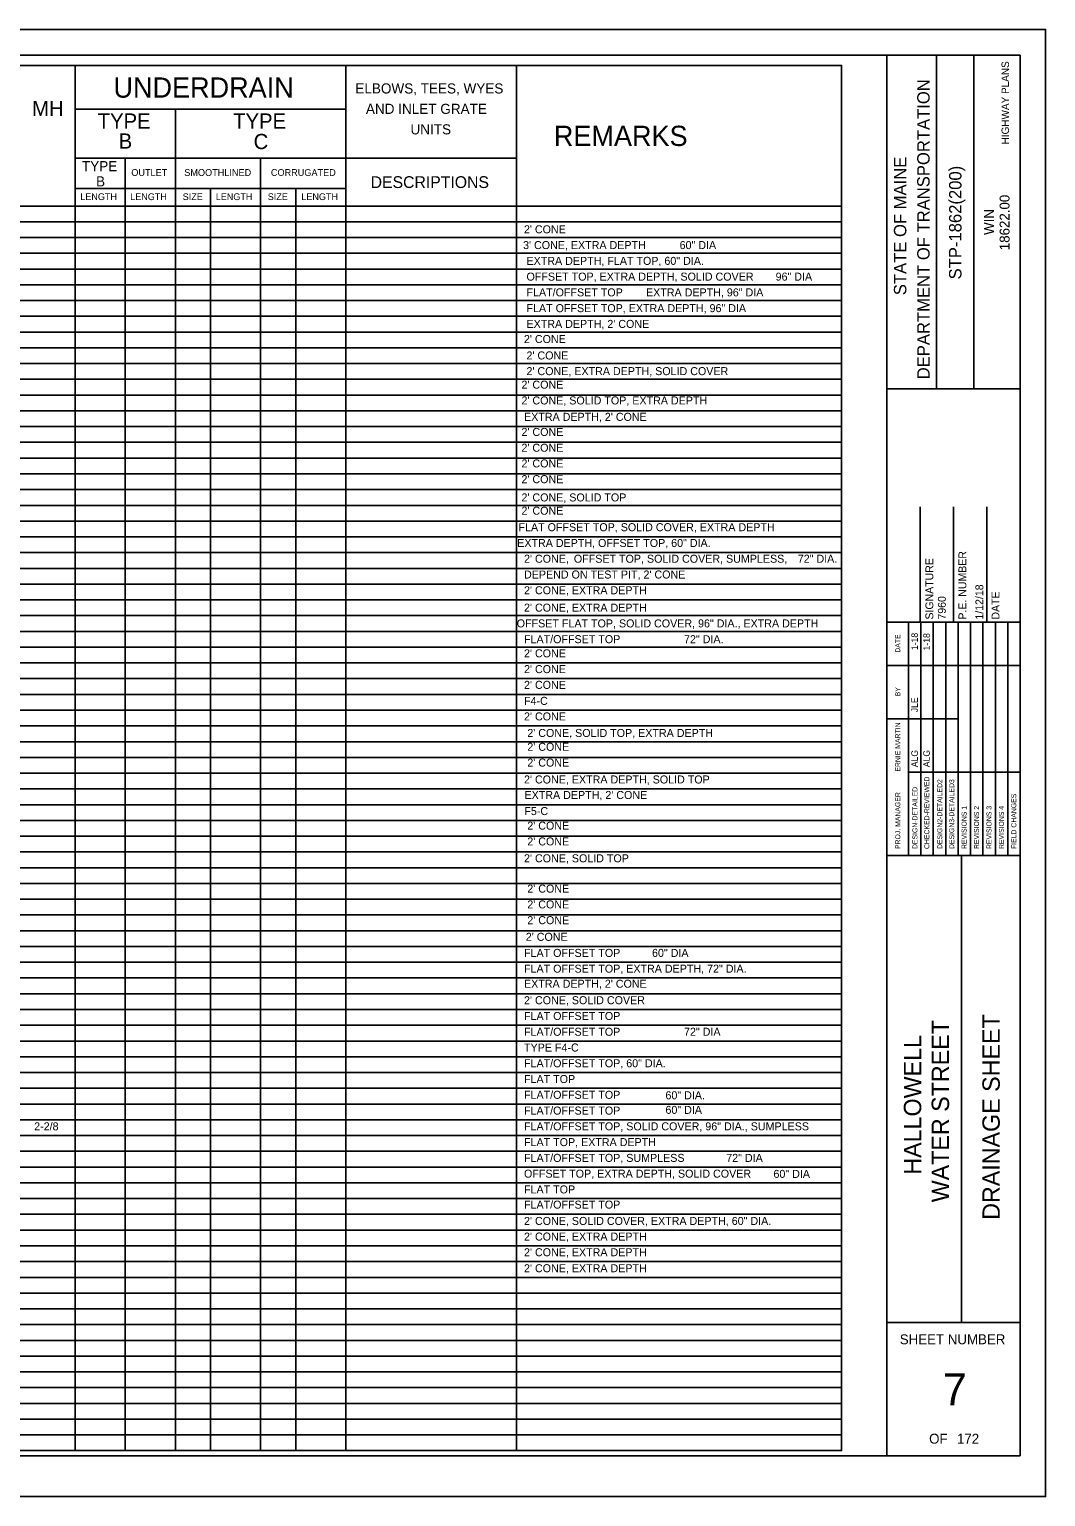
# Model space of a CAD drawing. Extents: x -0.13 to 2.7, y -0.05 to 1.78.
# Drawn here: x 1.428 to 2.698, y -0.051 to 1.782 of the extents above; entities that cross this region are included whole.
import ezdxf

# ---------------------------------------------------------------- set-up
doc = ezdxf.new("R2010")
doc.units = 0
for name, color, linetype in [('ANNOTATION', 7, 'Continuous'), ('BORDER', 7, 'Continuous'), ('PLOT BOUNDARY', 7, 'Continuous')]:
    doc.layers.add(name, color=color, linetype=linetype)

msp = doc.modelspace()

# ---------------------------------------------------------------- linework, layer by layer
at = {"layer": 'BORDER'}
for p, q in [((2.6667, 1.75), (0, 1.75)), ((2.5, 0), (2.5, 1.75)), ((2.5621, 1.3333), (2.5621, 1.75)), ((2.6087, 1.3333), (2.6087, 1.75)), ((2.6667, 0), (2.6667, 1.75)), ((1.4853, 1.6825), (1.4853, 1.7373)), ((1.8238, 1.6825), (1.8238, 1.7373)), ((2.0371, 1.6825), (2.0371, 1.7373)), ((1.4853, 1.6214), (1.4853, 1.6825)), ((1.4853, 1.6825), (1.548, 1.6825)), ((1.548, 1.6825), (1.6545, 1.6825)), ((1.6107, 1.6214), (1.6107, 1.6825)), ((1.6545, 1.6825), (1.7172, 1.6825)), ((1.7172, 1.6825), (1.7611, 1.6825)), ((1.7611, 1.6825), (1.8238, 1.6825)), ((1.8238, 1.6214), (1.8238, 1.6825)), ((2.0371, 1.6214), (2.0371, 1.6825)), ((1.4853, 1.5836), (1.4853, 1.6214)), ((1.4853, 1.6214), (1.548, 1.6214)), ((1.548, 1.5836), (1.548, 1.6214)), ((1.548, 1.6214), (1.6545, 1.6214)), ((1.6107, 1.5836), (1.6107, 1.6214)), ((1.6545, 1.6214), (1.7611, 1.6214)), ((1.7172, 1.5836), (1.7172, 1.6214)), ((1.7611, 1.6214), (1.8238, 1.6214)), ((1.8238, 1.5836), (1.8238, 1.6214)), ((1.8238, 1.6214), (2.0371, 1.6214)), ((2.0371, 1.5836), (2.0371, 1.6214)), ((1.4853, 1.5616), (1.4853, 1.5836)), ((1.4853, 1.5836), (1.548, 1.5836)), ((1.548, 1.5616), (1.548, 1.5836)), ((1.548, 1.5836), (1.6107, 1.5836)), ((1.6107, 1.5616), (1.6107, 1.5836)), ((1.6107, 1.5836), (1.6545, 1.5836)), ((1.6545, 1.5616), (1.6545, 1.5836)), ((1.6545, 1.5836), (1.7172, 1.5836)), ((1.7172, 1.5616), (1.7172, 1.5836)), ((1.7172, 1.5836), (1.7611, 1.5836)), ((1.7611, 1.5616), (1.7611, 1.5836)), ((1.7611, 1.5836), (1.8238, 1.5836)), ((1.8238, 1.5616), (1.8238, 1.5836)), ((2.0371, 1.5616), (2.0371, 1.5836)), ((1.4853, 1.5616), (1.4853, 0.0065)), ((1.548, 1.5616), (1.548, 0.0065)), ((1.6107, 1.5616), (1.6107, 0.0065)), ((1.6545, 1.5616), (1.6545, 0.0065)), ((1.7172, 1.5616), (1.7172, 0.0065)), ((1.7611, 1.5616), (1.7611, 0.0065)), ((1.8238, 1.5616), (1.8238, 0.0065)), ((2.0371, 1.5616), (2.0371, 0.0065)), ((0.0589, 1.5419), (2.4434, 1.5419)), ((0.0589, 1.5223), (2.4434, 1.5223)), ((0.0589, 1.5026), (2.4434, 1.5026)), ((0.0589, 1.4829), (2.4434, 1.4829)), ((0.0589, 1.4632), (2.4434, 1.4632)), ((0.0589, 1.4435), (2.4434, 1.4435)), ((0.0589, 1.4238), (2.4434, 1.4238)), ((0.0589, 1.4041), (2.4434, 1.4041)), ((0.0589, 1.3845), (2.4434, 1.3845)), ((0.0589, 1.3648), (2.4434, 1.3648)), ((0.0589, 1.3451), (2.4434, 1.3451)), ((0.0589, 1.3254), (2.4434, 1.3254)), ((2.5, 1.3332), (2.6667, 1.3332)), ((0.0589, 1.3057), (2.4434, 1.3057)), ((0.0589, 1.286), (2.4434, 1.286)), ((0.0589, 1.2664), (2.4434, 1.2664)), ((0.0589, 1.2467), (2.4434, 1.2467)), ((0.0589, 1.227), (2.4434, 1.227)), ((0.0589, 1.2073), (2.4434, 1.2073)), ((0.0589, 1.1876), (2.4434, 1.1876)), ((2.5417, 1.0417), (2.5417, 1.1858)), ((2.5833, 1.0417), (2.5833, 1.1858)), ((2.625, 1.0417), (2.625, 1.1858)), ((0.0589, 1.1679), (2.4434, 1.1679)), ((0.0589, 1.1482), (2.4434, 1.1482)), ((0.0589, 1.1286), (2.4434, 1.1286)), ((0.0589, 1.1089), (2.4434, 1.1089)), ((0.0589, 1.0892), (2.4434, 1.0892)), ((0.0589, 1.0695), (2.4434, 1.0695)), ((0.0589, 1.0498), (2.4434, 1.0498)), ((0.0589, 1.0301), (2.4434, 1.0301)), ((2.5, 1.0417), (2.6667, 1.0417)), ((0.0589, 1.0104), (2.4434, 1.0104)), ((0.0589, 0.9908), (2.4434, 0.9908)), ((0.0589, 0.9711), (2.4434, 0.9711)), ((0.0589, 0.9514), (2.4434, 0.9514)), ((0.0589, 0.9317), (2.4434, 0.9317)), ((0.0589, 0.912), (2.4434, 0.912)), ((0.0589, 0.8923), (2.4434, 0.8923)), ((0.0589, 0.8727), (2.4434, 0.8727)), ((0.0589, 0.853), (2.4434, 0.853)), ((0.0589, 0.8333), (2.4434, 0.8333)), ((0.0589, 0.8136), (2.4434, 0.8136)), ((0.0589, 0.7939), (2.4434, 0.7939)), ((0.0589, 0.7742), (2.4434, 0.7742)), ((0.0589, 0.7545), (2.4434, 0.7545)), ((0.0589, 0.7349), (2.4434, 0.7349)), ((2.5, 0.75), (2.6667, 0.75)), ((2.5932, 0.1667), (2.5932, 0.75)), ((0.0589, 0.7152), (2.4434, 0.7152)), ((0.0589, 0.6955), (2.4434, 0.6955)), ((0.0589, 0.6758), (2.4434, 0.6758)), ((0.0589, 0.6561), (2.4434, 0.6561)), ((0.0589, 0.6364), (2.4434, 0.6364)), ((0.0589, 0.6167), (2.4434, 0.6167)), ((0.0589, 0.5971), (2.4434, 0.5971)), ((0.0589, 0.5774), (2.4434, 0.5774)), ((0.0589, 0.5577), (2.4434, 0.5577)), ((0.0589, 0.538), (2.4434, 0.538)), ((0.0589, 0.5183), (2.4434, 0.5183)), ((0.0589, 0.4986), (2.4434, 0.4986)), ((0.0589, 0.479), (2.4434, 0.479)), ((0.0589, 0.4593), (2.4434, 0.4593)), ((0.0589, 0.4396), (2.4434, 0.4396)), ((0.0589, 0.4199), (2.4434, 0.4199)), ((0.0589, 0.4002), (2.4434, 0.4002)), ((0.0589, 0.3805), (2.4434, 0.3805)), ((0.0589, 0.3608), (2.4434, 0.3608)), ((0.0589, 0.3412), (2.4434, 0.3412)), ((0.0589, 0.3215), (2.4434, 0.3215)), ((0.0589, 0.3018), (2.4434, 0.3018)), ((0.0589, 0.2821), (2.4434, 0.2821)), ((0.0589, 0.2624), (2.4434, 0.2624)), ((0.0589, 0.2427), (2.4434, 0.2427)), ((0.0589, 0.223), (2.4434, 0.223)), ((0.0589, 0.2034), (2.4434, 0.2034)), ((0.0589, 0.1837), (2.4434, 0.1837)), ((2.5, 0.1667), (2.6667, 0.1667)), ((0.0589, 0.164), (2.4434, 0.164)), ((0.0589, 0.1443), (2.4434, 0.1443)), ((0.0589, 0.1246), (2.4434, 0.1246)), ((0.0589, 0.1049), (2.4434, 0.1049)), ((0.0589, 0.0853), (2.4434, 0.0853)), ((0.0589, 0.0656), (2.4434, 0.0656)), ((0.0589, 0.0459), (2.4434, 0.0459)), ((0.0589, 0.0262), (2.4434, 0.0262)), ((0, 0), (2.6667, 0)), ((0.0589, 0.0065), (2.3003, 0.0065))]:
    msp.add_line(p, q, dxfattribs=at)
msp.add_lwpolyline([(0.0589, 1.7373), (2.4434, 1.7373), (2.4434, 1.5616), (0.0589, 1.5616)], close=True, dxfattribs=at)
for points in [[(0.0589, 1.5616), (0.0589, 0.0065), (2.4434, 0.0065), (2.4434, 1.5616)], [(2.5269, 0.9875), (2.5269, 1.0417)], [(2.5269, 0.7501), (2.5269, 1.0299)], [(2.5425, 0.7501), (2.5425, 1.0417)], [(2.558, 1.0417), (2.558, 0.7501)], [(2.5735, 0.7501), (2.5735, 1.0417)], [(2.589, 0.7501), (2.589, 1.0417)], [(2.6046, 0.7501), (2.6046, 1.0417)], [(2.6201, 0.7501), (2.6201, 1.0417)], [(2.6356, 0.7501), (2.6356, 1.0417)], [(2.6512, 0.7501), (2.6512, 1.0417)], [(2.5, 0.9875), (2.6667, 0.9875)], [(2.5, 0.9209), (2.5269, 0.9209)], [(2.5269, 0.9209), (2.589, 0.9209)], [(2.5269, 0.8542), (2.6667, 0.8542)]]:
    msp.add_lwpolyline(points, dxfattribs=at)
at = {"layer": 'PLOT BOUNDARY'}
msp.add_lwpolyline([(-0.1349, -0.051), (2.6984, -0.051), (2.6984, 1.7823), (-0.1349, 1.7823)], close=True, dxfattribs=at)

# ---------------------------------------------------------------- texts
at = {"layer": 'ANNOTATION'}
for s, p in [("2' CONE", (2.0463, 1.5275)), ("3' CONE, EXTRA DEPTH", (2.0452, 1.5078)), ('60" DIA', (2.2409, 1.5078)), ('EXTRA DEPTH, FLAT TOP, 60" DIA.', (2.0495, 1.4881)), ('OFFSET TOP, EXTRA DEPTH, SOLID COVER', (2.0495, 1.4684)), ('96" DIA', (2.3609, 1.4684)), ('FLAT/OFFSET TOP', (2.0495, 1.4487)), ('EXTRA DEPTH, 96" DIA', (2.1989, 1.4487)), ('FLAT OFFSET TOP, EXTRA DEPTH, 96" DIA', (2.0495, 1.429)), ("EXTRA DEPTH, 2' CONE", (2.0495, 1.4093)), ("2' CONE", (2.0463, 1.3904)), ("2' CONE", (2.0495, 1.3699)), ("2' CONE, EXTRA DEPTH, SOLID COVER", (2.0495, 1.3503)), ("2' CONE", (2.0432, 1.3334)), ("2' CONE, SOLID TOP, EXTRA DEPTH", (2.0432, 1.3137)), ("EXTRA DEPTH, 2' CONE", (2.0464, 1.2932)), ("2' CONE", (2.0432, 1.2743)), ("2' CONE", (2.0432, 1.2546)), ("2' CONE", (2.0432, 1.235)), ("2' CONE", (2.0432, 1.2153)), ("2' CONE, SOLID TOP", (2.0432, 1.1925)), ("2' CONE", (2.0432, 1.1759)), ('FLAT OFFSET TOP, SOLID COVER, EXTRA DEPTH', (2.0395, 1.1553)), ('EXTRA DEPTH, OFFSET TOP, 60" DIA.', (2.0379, 1.1356)), ("2' CONE,", (2.0464, 1.1159)), ('OFFSET TOP, SOLID COVER, SUMPLESS,', (2.1087, 1.1159)), ('72" DIA.', (2.3886, 1.1159)), ("DEPEND ON TEST PIT, 2' CONE", (2.0464, 1.0962)), ("2' CONE, EXTRA DEPTH", (2.0464, 1.0765)), ("2' CONE, EXTRA DEPTH", (2.0464, 1.0548)), ('OFFSET FLAT TOP, SOLID COVER, 96" DIA., EXTRA DEPTH', (2.0373, 1.0351)), ('FLAT/OFFSET TOP', (2.0464, 1.0154)), ('72" DIA.', (2.2464, 1.0154)), ("2' CONE", (2.0464, 0.9977)), ("2' CONE", (2.0464, 0.978)), ("2' CONE", (2.0464, 0.9583)), ('F4-C', (2.0464, 0.9383)), ("2' CONE", (2.0464, 0.9189)), ("2' CONE, SOLID TOP, EXTRA DEPTH", (2.0505, 0.8982)), ("2' CONE", (2.0505, 0.8809)), ("2' CONE", (2.0505, 0.8612)), ("2' CONE, EXTRA DEPTH, SOLID TOP", (2.0464, 0.8401)), ("EXTRA DEPTH, 2' CONE", (2.047, 0.8207)), ('F5-C', (2.0468, 0.8006)), ("2' CONE", (2.0505, 0.7824)), ("2' CONE", (2.0505, 0.7627)), ("2' CONE, SOLID TOP", (2.0464, 0.7416)), ("2' CONE", (2.0505, 0.7037)), ("2' CONE", (2.0505, 0.684)), ("2' CONE", (2.0505, 0.6643)), ("2' CONE", (2.0486, 0.6435)), ('FLAT OFFSET TOP', (2.0464, 0.6234)), ('60" DIA', (2.2064, 0.6234)), ('FLAT OFFSET TOP, EXTRA DEPTH, 72" DIA.', (2.0464, 0.6037)), ("EXTRA DEPTH, 2' CONE", (2.0464, 0.5849)), ("2' CONE, SOLID COVER", (2.0464, 0.5643)), ('FLAT OFFSET TOP', (2.0464, 0.5446)), ('FLAT/OFFSET TOP', (2.0464, 0.5249)), ('72" DIA', (2.2464, 0.5249)), ('TYPE F4-C', (2.0464, 0.5052)), ('FLAT/OFFSET TOP, 60" DIA.', (2.0464, 0.4855)), ('FLAT TOP', (2.0464, 0.4658)), ('FLAT/OFFSET TOP', (2.0464, 0.4461)), ('60" DIA.', (2.2232, 0.4455)), ('FLAT/OFFSET TOP', (2.0464, 0.4264)), ('60" DIA', (2.2232, 0.4273)), ('2-2/8', (1.4341, 0.4067)), ('FLAT/OFFSET TOP, SOLID COVER, 96" DIA., SUMPLESS', (2.0464, 0.4067)), ('FLAT TOP, EXTRA DEPTH', (2.0464, 0.387)), ('FLAT/OFFSET TOP, SUMPLESS', (2.0464, 0.3673)), ('72" DIA', (2.2992, 0.3673)), ('OFFSET TOP, EXTRA DEPTH, SOLID COVER', (2.0464, 0.3476)), ('60" DIA', (2.3582, 0.3473)), ('FLAT TOP', (2.0464, 0.3279)), ('FLAT/OFFSET TOP', (2.0464, 0.3089)), ('2\' CONE, SOLID COVER, EXTRA DEPTH, 60" DIA.', (2.0464, 0.2885)), ("2' CONE, EXTRA DEPTH", (2.0464, 0.269)), ("2' CONE, EXTRA DEPTH", (2.0464, 0.2494)), ("2' CONE, EXTRA DEPTH", (2.0464, 0.2294))]:
    msp.add_text(s, height=0.01, dxfattribs=at).set_placement(p)
at = {"layer": 'BORDER'}
for s, height, p in [('HIGHWAY PLANS', 0.009317, (2.6526, 1.6386)), ('DEPARTMENT OF TRANSPORTATION', 0.015529, (2.5534, 1.3451)), ('STATE OF MAINE', 0.015529, (2.5243, 1.4502)), ('STP-1862(200)', 0.015529, (2.5932, 1.4699)), ('18622.00', 0.01242, (2.6533, 1.5064)), ('WIN', 0.01242, (2.6339, 1.5255)), ('SIGNATURE', 0.00984, (2.558, 1.0449)), ('P.E. NUMBER', 0.009843, (2.5993, 1.0449)), ('1/12/18', 0.00984, (2.6205, 1.0449)), ('7960', 0.00984, (2.5736, 1.0449)), ('DATE', 0.00984, (2.6407, 1.0449)), ('1-18', 0.00808, (2.5387, 1.0067)), ('1-18', 0.00808, (2.5536, 1.0063)), ('DATE', 0.00619, (2.5167, 1.0035)), ('BY', 0.00619, (2.5167, 0.949)), ('JLE', 0.00808, (2.5387, 0.929)), ('ERNIE MARTIN', 0.006212, (2.5167, 0.8549)), ('ALG', 0.00808, (2.5387, 0.8604)), ('ALG', 0.00808, (2.5536, 0.8604)), ('CHECKED-REVIEWED', 0.006212, (2.553, 0.7582)), ('PROJ. MANAGER', 0.006212, (2.5167, 0.7582)), ('DESIGN-DETAILED', 0.006212, (2.5381, 0.7582)), ('DESIGN2-DETAILED2', 0.006212, (2.5692, 0.7582)), ('DESIGN3-DETAILED3', 0.006212, (2.5841, 0.7582)), ('REVISIONS 1', 0.006212, (2.5996, 0.7582)), ('REVISIONS 2', 0.006212, (2.6151, 0.7582)), ('REVISIONS 3', 0.006212, (2.6307, 0.7582)), ('REVISIONS 4', 0.006212, (2.6462, 0.7582)), ('FIELD CHANGES', 0.006212, (2.6617, 0.7582)), ('DRAINAGE SHEET', 0.021738, (2.6411, 0.2949)), ('WATER STREET', 0.021738, (2.5777, 0.3168)), ('HALLOWELL', 0.02174, (2.5429, 0.3513))]:
    msp.add_text(s, height=height, rotation=90, dxfattribs=at).set_placement(p)
for s, height, p in [('UNDERDRAIN', 0.02528, (1.5332, 1.697)), ('ELBOWS, TEES, WYES', 0.012638, (1.8356, 1.7022)), ('MH', 0.01896, (1.4315, 1.674)), ('AND INLET GRATE', 0.012638, (1.8488, 1.6767)), ('TYPE', 0.01896, (1.5135, 1.6583)), ('TYPE', 0.01896, (1.6828, 1.6583)), ('B', 0.019, (1.5397, 1.6333)), ('C', 0.019, (1.7084, 1.6327)), ('UNITS', 0.01264, (1.9045, 1.6511)), ('REMARKS', 0.02528, (2.0837, 1.6366)), ('TYPE', 0.01264, (1.4938, 1.6051)), ('B', 0.0126, (1.5115, 1.5861)), ('OUTLET', 0.00853, (1.5555, 1.5992)), ('SMOOTHLINED', 0.008531, (1.6217, 1.5992)), ('CORRUGATED', 0.00853, (1.73, 1.5992)), ('DESCRIPTIONS', 0.014744, (1.8547, 1.5841)), ('LENGTH', 0.00843, (1.4918, 1.569)), ('LENGTH', 0.00843, (1.5542, 1.569)), ('SIZE', 0.00843, (1.6198, 1.569)), ('LENGTH', 0.00843, (1.6611, 1.569)), ('SIZE', 0.00843, (1.7261, 1.569)), ('LENGTH', 0.00843, (1.7681, 1.569)), ('SHEET NUMBER', 0.012421, (2.5161, 0.1394)), ('7', 0.0403, (2.5698, 0.063)), ('OF', 0.01242, (2.5528, 0.0152)), ('172', 0.01242, (2.5876, 0.0152))]:
    msp.add_text(s, height=height, dxfattribs=at).set_placement(p)

doc.saveas('drawing.dxf')
